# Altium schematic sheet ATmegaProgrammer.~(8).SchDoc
size A4
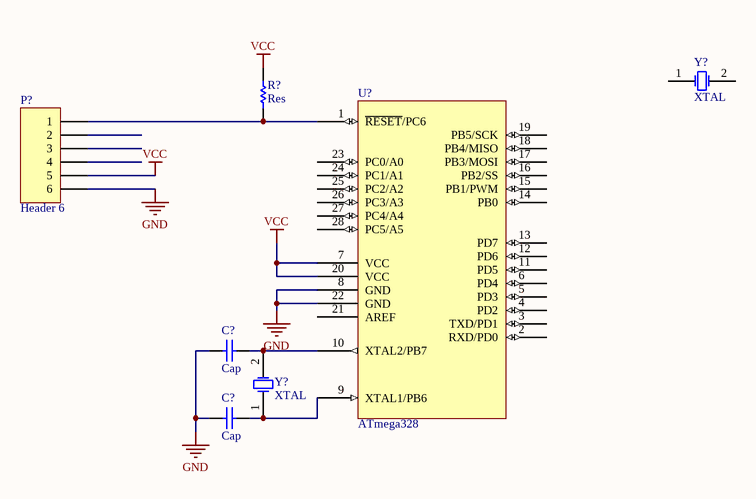
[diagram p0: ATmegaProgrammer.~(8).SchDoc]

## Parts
(Parts that share a designator on the sheet are numbered #1, #2 ... from top to bottom, then left to right.)
C?#1  Cap  [C200]
C?#2  Cap  [C200]
P?  Header 6  [HDR1X6]
R?  Res  [AXIAL-0.3]
U?  ATmega328  [DIP28]
Y?#1  XTAL  [XTAL4-8]
Y?#2  XTAL  [XTAL4-8]

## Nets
GND: C?#1.1 C?#2.1 P?.6 U?.8(GND) U?.22(GND)
VCC: P?.5 R?.2 U?.7(VCC) U?.20(VCC)
NetC?#1_2: C?#1.2 U?.10(XTAL2/PB7) Y?#2.2(OSC2)
NetC?#2_2: C?#2.2 U?.9(XTAL1/PB6) Y?#2.1(OSC1)
NetP?_1: P?.1 R?.1 U?.1(~{RESET}/PC6)

Not connected (* = marked no-connect by the designer): P? 2 3 4; U? 2(RXD/PD0) 3(TXD/PD1) 4(PD2) 5(PD3) 6(PD4) 11(PD5) 12(PD6) 13(PD7) 14(PB0) 15(PB1/PWM) 16(PB2/SS) 17(PB3/MOSI) 18(PB4/MISO) 19(PB5/SCK) 21(AREF) 23(PC0/A0) 24(PC1/A1) 25(PC2/A2) 26(PC3/A3) 27(PC4/A4) 28(PC5/A5); Y?#1 1(OSC1) 2(OSC2)

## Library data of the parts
C?#1 C?#2 = Cap: Capacitor
P? = Header 6: Header, 6-Pin
R? = Res: Resistor
U? = ATmega328: ATmega¨t¦C³æ´¹¤ù
Y?#1 Y?#2 = XTAL: Crystal Oscillator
